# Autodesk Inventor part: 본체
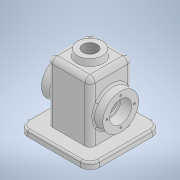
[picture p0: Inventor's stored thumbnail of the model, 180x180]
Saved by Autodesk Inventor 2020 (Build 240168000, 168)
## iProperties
Created: 2021-07
Part Number: 본체
Material: 일반
Document SubType Name: Modeling
Designer: Owner
Density: 1 g/cm^3
Appearance: 기본값
Author: Owner
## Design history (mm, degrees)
sketch "스케치1"
  geometry: L1 (34, 34)-(-34, 34); L2 (-34, 34)-(-34, -34); L3 (-34, -34)-(34, -34); L4 (34, -34)-(34, 34); L5 (34, 34)-(-34, -34); L6 (-34, 34)-(34, -34); 1 further point
  constraints: 12 end point, 2 midpoint, 2 parallel, 1 horizontal, 1 perpendicular
  dimensions: "d0" = 68 distance of L3.end L2.end; "d1" = 68 distance of L2.end L1.end
extrude "돌출1" new body sketch "스케치1" distance "d2" = 105; taper "d3" = 0 deg
fillet "모깎기1" dims "d4" = 8
feature "쉘1" dims "d5" = 5
sketch "스케치2"
  geometry: L1 (-57, 57)-(57, 57); L2 (57, 57)-(57, -57); L3 (57, -57)-(-57, -57); L4 (-57, -57)-(-57, 57); L5 (-57, 57)-(57, -57); L6 (57, 57)-(-57, -57); L7 (-26, 29)-(26, 29) reference; L8 (29, 26)-(29, -26) reference; L9 (26, -29)-(-26, -29) reference; L10 (-29, -26)-(-29, 26) reference; L11 (34, 26)-(34, -26) reference; L12 (-26, 34)-(26, 34) reference; L13 (-34, -26)-(-34, 26) reference; L14 (26, -34)-(-26, -34) reference; A1 r 3 centre (-26, 26) between (-26, 29) and (-29, 26) reference; A2 r 3 centre (26, 26) between (29, 26) and (26, 29) reference; A3 r 3 centre (26, -26) between (26, -29) and (29, -26) reference; A4 r 3 centre (-26, -26) between (-29, -26) and (-26, -29) reference; A5 r 8 centre (26, -26) between (26, -34) and (34, -26) reference; A6 r 8 centre (26, 26) between (34, 26) and (26, 34) reference; A7 r 8 centre (-26, 26) between (-26, 34) and (-34, 26) reference; A8 r 8 centre (-26, -26) between (-34, -26) and (-26, -34) reference; 1 further point
  constraints: 12 end point, 2 midpoint, 2 parallel, 1 horizontal, 1 perpendicular
  dimensions: "d6" = 114 distance of L2.end L3.end; "d7" = 114 distance of L1.end L2.end
extrude "돌출2" join sketch "스케치2" distance "d8" = 10; taper "d9" = 0 deg
fillet "모깎기2" dims "d10" = 15
fillet "모깎기3" dims "d11" = 3
node "작업 평면1"
sketch "스케치3"
  geometry: L1 (68, -97)-(-16, -97) reference; C1 r 28.5 at (26, -45); 2 further points
  constraints: 1 centre point, 1 midpoint, 1 vertical alignment
  dimensions: "d13" = 52 distance from line of L1 C1.centre; "d14" = 57 diameter of C1
extrude "돌출4" join sketch "스케치3" stored distance "d17" = 10; taper "d18" = 0 deg
fillet "모깎기4" dims "d19" = 3
sketch "스케치4"
  geometry: C1 r 28.5 at (0, 0) reference; C2 r 17.5 at (0, 0); 1 further point
  constraints: 1 centre point, 1 coincident
  dimensions: "d20" = 35 diameter of C2
extrude "돌출5" cut sketch "스케치4" distance "d21" = 17; taper "d22" = 0 deg
sketch "스케치5"
  geometry: C1 r 17.5 at (0, 0) reference; C2 r 15 at (0, 0)
  constraints: 1 centre point, 1 coincident
  dimensions: "d23" = 30 diameter of C2
extrude "돌출6" cut sketch "스케치5" distance "d24" = 3; taper "d25" = 0 deg
node "작업 평면2"
node "작업 평면3"
node "작업 평면4"
node "작업 평면5"
sketch "스케치6"
  geometry: L1 (68, -97)-(-16, -97) reference; C1 r 28.5 at (26, -45); 2 further points
  constraints: 1 centre point, 1 midpoint, 1 vertical alignment
  dimensions: "d28" = 52 distance from line of L1 C1.centre; "d29" = 57 diameter of C1
extrude "돌출7" join sketch "스케치6" stored distance "d30" = 3; taper "d31" = 0 deg
sketch "스케치7"
  geometry: C1 r 28.5 at (0, 0) reference; C2 r 17.5 at (0, 0) reference; C3 r 17.5 at (0, 0); 1 further point
  constraints: 1 centre point, 1 coincident
  dimensions: "d32" = 35 diameter of C3
extrude "돌출8" cut sketch "스케치7" distance "d33" = 17; taper "d34" = 0 deg
sketch "스케치8"
  geometry: C1 r 17.5 at (0, 0) reference; C2 r 28.5 at (0, 0) reference; C3 r 17.5 at (0, 0) reference; C4 r 15 at (0, 0); 1 further point
  constraints: 1 centre point, 1 coincident
  dimensions: "d35" = 30 diameter of C4
extrude "돌출9" cut sketch "스케치8" distance "d36" = 3; taper "d37" = 0 deg
fillet "모깎기5" dims "d38" = 3
sketch "스케치9"
  geometry: C1 r 28.5 at (0, 0) reference; 2 further points
  constraints: 1 vertical alignment
  dimensions: "d39" = 22 distance of C1.centre point (0, 22)
hole "구멍1" sketch "스케치9" at (0, 22) diameter "d40" = 3.242; stored, may be unused: countersink angle "d44" = 90 deg, drill point angle "d46" = 118 deg; dims "d41" = 8, "d42" = 4, "d43" = 2, "d45" = 10
node "작업 평면6"
sketch "스케치10"
  geometry: C1 r 20 at (0, 0); 1 further point
  constraints: 1 centre point, 1 coincident
  dimensions: "d51" = 40 diameter of C1
extrude "돌출10" join sketch "스케치10" stored distance "d52" = 3; taper "d53" = 8 deg
sketch "스케치11"
  geometry: C1 r 20 at (0, 0) reference; 2 further points
  constraints: 1 coincident
hole "구멍2" sketch "스케치11" at (0, 0) diameter "d54" = 22.83494; stored, may be unused: countersink angle "d58" = 90 deg, drill point angle "d60" = 0 deg; dims "d55" = 50, "d56" = 4, "d57" = 2, "d59" = 59.3
node "솔리드1"
pattern_circular "원형 패턴1" dims angle "d48" = 360 deg
mirror "미러1"
node "투영된 루프1"
node "투영된 루프2"
feature "A9D066F2-1C7D-4E18-AEED-F7BC21143FA4" dims "d40" = 3.242, "d41" = 8, "d42" = 4, "d43" = 2, "d44" = 90 deg, "d45" = 10, "d46" = 118 deg
other parameters: "d12" = 15, "d26" = 15, "d27" = 15, "d50" = 115
